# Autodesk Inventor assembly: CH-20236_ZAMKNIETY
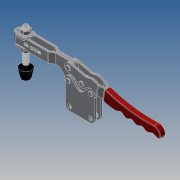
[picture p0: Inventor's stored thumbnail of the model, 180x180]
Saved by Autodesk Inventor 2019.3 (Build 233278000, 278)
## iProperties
Company: ·L?¤¤?
Created: 2010-06
Part Number: CH-20236_ZAMKNIETY
Material: Ogólny
Description: STEP AP203
Document SubType Name: Assembly
Designer: CADENGINEERING4
Sending System: SolidWorks 2005179
Preprocessor: SwSTEP 2.0
Title: CH-20236.STEP
Author: ·L?¥Î?
Revision Number: ANY
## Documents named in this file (9)
- E:\STRONA\Horizontal toggle clamp\CH-20236\CH-20236_ZAMKNIETY.iam
- E:\STRONA\Horizontal toggle clamp\CH-20236\20235-03___.ipt
- E:\STRONA\Horizontal toggle clamp\CH-20236\38312-02___.ipt
- E:\STRONA\Horizontal toggle clamp\CH-20236\FW380___.ipt
- E:\STRONA\Horizontal toggle clamp\CH-20236\20235-04___.ipt
- E:\STRONA\Horizontal toggle clamp\CH-20236\20235-05___.ipt
- E:\STRONA\Horizontal toggle clamp\CH-20236\20236-01___.ipt
- E:\STRONA\Horizontal toggle clamp\CH-20236\20236-02___.ipt
- E:\STRONA\Horizontal toggle clamp\CH-20236\CH-FC-38312___.ipt
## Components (14 placed, 14 different names)
1. 20235-03_??_1 — Zestawiające:14, Zestawiające:16, Zestawiające:18, Zestawiające:19, Zestawiające:25, Zestawiające:26, Zestawiające:27, Przejściowe:1
2. 38312-02_??_2 — Równoległe:1, Zestawiające:1, Zestawiające:3
3. FW380_??_3 — Równoległe:3, Zestawiające:5, Zestawiające:6, Zestawiające:8
4. 20235-04_??_4 — Zestawiające:10, Zestawiające:11, Zestawiające:12
5. 38312-02_??_5 — Zestawiające:6, Zestawiające:7
6. FW380_??_6 — Równoległe:2, Równoległe:3, Zestawiające:2, Zestawiające:3, Zestawiające:4
7. 20235-05_??_7 — Zestawiające:23, Zestawiające:24
8. 20235-05_??_8 — Zestawiające:18, Zestawiające:19
9. 20236-01_??_9 — Zestawiające:13, Zestawiające:15, Zestawiające:17, Zestawiające:20, Zestawiające:21, Zestawiające:22, Zestawiające:23, Zestawiające:24, Przejściowe:1
10. 20236-02_??_10 — Równoległe:2, Zestawiające:4, Zestawiające:8, Zestawiające:9, Zestawiające:21, Zestawiające:22, Zestawiające:25
11. 20235-05_??_11 — Zestawiające:26, Zestawiające:27
12. 20235-04_??_12 — Zestawiające:10, Zestawiające:11, Zestawiające:12, Zestawiające:13, Zestawiające:14, Zestawiające:15, Zestawiające:16
13. CH-FC-38312_??_13 — Równoległe:1, Zestawiające:1, Zestawiające:2, Zestawiające:5, Zestawiające:7, Zestawiające:9
14. 20235-05_??_14 — Zestawiające:17, Zestawiające:20
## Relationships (31: Mate 27, Flush 3, Transitional 1)
- Równoległe:1 [Flush]: 38312-02_??_2 ↔ CH-FC-38312_??_13
- Równoległe:2 [Flush]: FW380_??_6 ↔ 20236-02_??_10
- Równoległe:3 [Flush]: FW380_??_3 ↔ FW380_??_6
- Zestawiające:1 [Mate]: 38312-02_??_2 ↔ CH-FC-38312_??_13
- Zestawiające:2 [Mate]: FW380_??_6 ↔ CH-FC-38312_??_13
- Zestawiające:3 [Mate]: 38312-02_??_2 ↔ FW380_??_6
- Zestawiające:4 [Mate]: FW380_??_6 ↔ 20236-02_??_10
- Zestawiające:5 [Mate]: FW380_??_3 ↔ CH-FC-38312_??_13
- Zestawiające:6 [Mate]: FW380_??_3 ↔ 38312-02_??_5
- Zestawiające:7 [Mate]: 38312-02_??_5 ↔ CH-FC-38312_??_13
- Zestawiające:8 [Mate]: FW380_??_3 ↔ 20236-02_??_10
- Zestawiające:9 [Mate]: 20236-02_??_10 ↔ CH-FC-38312_??_13
- Zestawiające:10 [Mate]: 20235-04_??_4 ↔ 20235-04_??_12
- Zestawiające:11 [Mate]: 20235-04_??_4 ↔ 20235-04_??_12
- Zestawiające:12 [Mate]: 20235-04_??_4 ↔ 20235-04_??_12
- Zestawiające:13 [Mate]: 20236-01_??_9 ↔ 20235-04_??_12
- Zestawiające:14 [Mate]: 20235-03_??_1 ↔ 20235-04_??_12
- Zestawiające:15 [Mate]: 20236-01_??_9 ↔ 20235-04_??_12
- Zestawiające:16 [Mate]: 20235-03_??_1 ↔ 20235-04_??_12
- Zestawiające:17 [Mate]: 20236-01_??_9 ↔ 20235-05_??_14
- Zestawiające:18 [Mate]: 20235-03_??_1 ↔ 20235-05_??_8
- Zestawiające:19 [Mate]: 20235-03_??_1 ↔ 20235-05_??_8
- Zestawiające:20 [Mate]: 20236-01_??_9 ↔ 20235-05_??_14
- Zestawiające:21 [Mate]: 20236-01_??_9 ↔ 20236-02_??_10
- Zestawiające:22 [Mate]: 20236-01_??_9 ↔ 20236-02_??_10
- Zestawiające:23 [Mate]: 20235-05_??_7 ↔ 20236-01_??_9
- Zestawiające:24 [Mate]: 20235-05_??_7 ↔ 20236-01_??_9
- Zestawiające:25 [Mate]: 20235-03_??_1 ↔ 20236-02_??_10
- Zestawiające:26 [Mate]: 20235-03_??_1 ↔ 20235-05_??_11
- Zestawiające:27 [Mate]: 20235-03_??_1 ↔ 20235-05_??_11
- Przejściowe:1 [Transitional]: 20235-03_??_1 ↔ 20236-01_??_9
